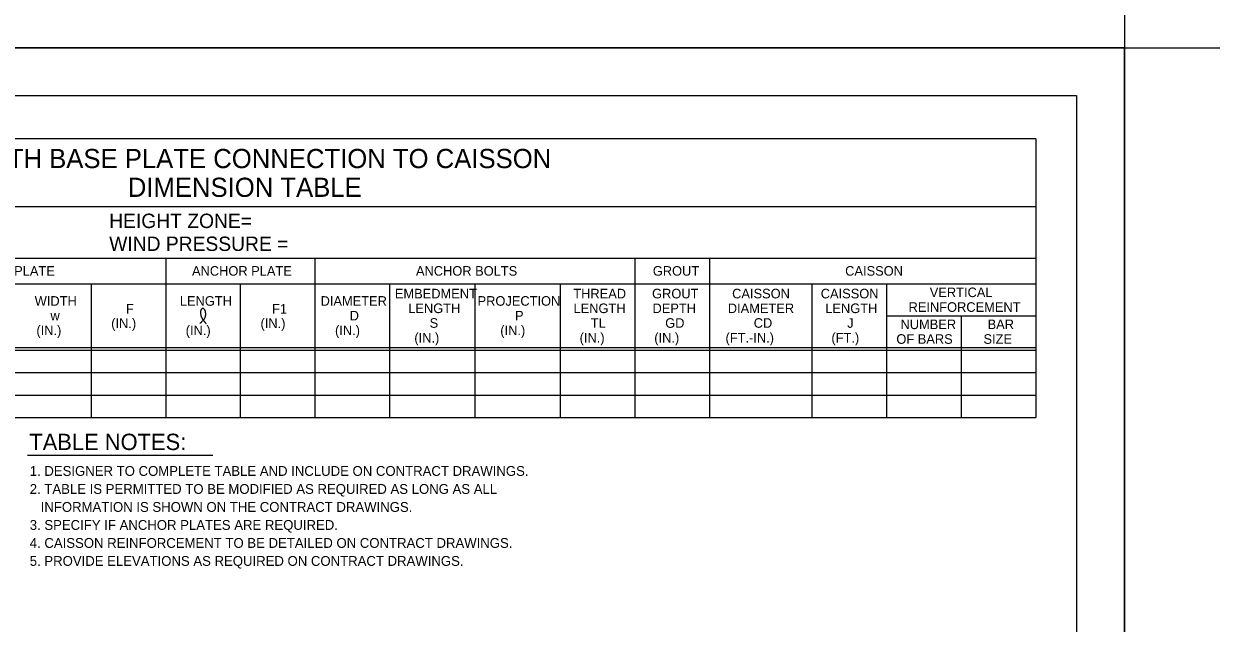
# Model space of a CAD drawing. Extents: x 3475 to 6558, y -3780 to 1166.
# Drawn here: x 4258.3 to 4629.5, y -202.4 to -14.8 of the extents above; entities that cross this region are included whole.
import ezdxf

# ---------------------------------------------------------------- set-up
doc = ezdxf.new("R2010")
doc.units = 0
for name, color, linetype in [('1', 7, 'Continuous'), ('2', 7, 'Continuous'), ('PLT-BNDY', 7, 'Continuous')]:
    doc.layers.add(name, color=color, linetype=linetype)

msp = doc.modelspace()

# ---------------------------------------------------------------- linework, layer by layer
at = {"layer": '1'}
for p, q in [((4574.64, -50.81), (4094.64, -50.81)), ((4574.64, -50.81), (4574.64, -138.01)), ((4574.64, -72.14), (4094.64, -72.14)), ((4094.64, -88.14), (4574.64, -88.14)), ((4302.64, -88.14), (4302.64, -138.01)), ((4349.3, -88.14), (4349.3, -138.01)), ((4449.3, -88.14), (4449.3, -138.01)), ((4472.64, -88.14), (4472.64, -138.01)), ((4094.64, -96.14), (4574.64, -96.14)), ((4279.31, -96.14), (4279.31, -138.01)), ((4325.97, -96.14), (4325.97, -138.01)), ((4372.64, -96.14), (4372.64, -138.01)), ((4399.3, -96.14), (4399.3, -138.01)), ((4425.97, -96.14), (4425.97, -138.01)), ((4504.64, -96.14), (4504.64, -138.01)), ((4527.97, -96.14), (4527.97, -138.01)), ((4527.97, -106.16), (4574.64, -106.16)), ((4551.31, -106.16), (4551.31, -138.01)), ((4094.64, -116.14), (4574.64, -116.14)), ((4094.64, -116.89), (4574.64, -116.89)), ((4094.64, -123.93), (4574.64, -123.93)), ((4094.64, -130.97), (4574.64, -130.97)), ((4094.64, -138.01), (4574.64, -138.01)), ((4259.47, -149.81), (4317.41, -149.81))]:
    msp.add_line(p, q, dxfattribs=at)
msp.add_spline([(4313.36, -108.55), (4313.56, -108.39), (4313.69, -108.25), (4313.89, -108.06), (4314.05, -107.89), (4314.33, -107.68), (4314.52, -107.43), (4314.7, -107.23), (4314.82, -107), (4314.93, -106.75), (4315.01, -106.52), (4315.09, -106.29), (4315.12, -106.09), (4315.15, -105.84), (4315.16, -105.62), (4315.15, -105.38), (4315.1, -105.13), (4315.06, -104.88), (4315, -104.65), (4314.91, -104.43), (4314.84, -104.29), (4314.74, -104.19), (4314.64, -104.1), (4314.55, -104.01), (4314.44, -103.95), (4314.35, -103.93), (4314.18, -103.93), (4314.09, -103.95), (4313.94, -104), (4313.84, -104.08), (4313.78, -104.17), (4313.72, -104.29), (4313.65, -104.4), (4313.61, -104.55), (4313.58, -104.65), (4313.54, -104.89), (4313.52, -105.06), (4313.54, -105.26), (4313.54, -105.45), (4313.58, -105.73), (4313.6, -105.96), (4313.64, -106.13), (4313.71, -106.35), (4313.81, -106.58), (4313.9, -106.77), (4314, -106.97), (4314.12, -107.2), (4314.32, -107.38), (4314.44, -107.59), (4314.57, -107.74), (4314.68, -107.92), (4314.82, -108.09), (4314.96, -108.27), (4315.06, -108.37), (4315.18, -108.51), (4315.28, -108.67)], degree=3, dxfattribs=at)
at = {"layer": '2'}
for p, q in [((3801.34, -37.31), (4587.34, -37.31)), ((4587.34, -37.31), (4587.34, -601.31))]:
    msp.add_line(p, q, dxfattribs=at)
at = {"layer": 'PLT-BNDY'}
for points in [[(3761.34, 571.69), (4602.34, 571.69), (4602.34, -22.31), (3761.34, -22.31)], [(3761.34, -22.31), (4602.34, -22.31), (4602.34, -616.31), (3761.34, -616.31)], [(4602.34, -22.31), (5443.34, -22.31), (5443.34, -616.31), (4602.34, -616.31)]]:
    msp.add_lwpolyline(points, close=True, dxfattribs=at)

# ---------------------------------------------------------------- texts
at = {"layer": '1'}
for s, height, p in [('STEEL POST WITH BASE PLATE CONNECTION TO CAISSON', 6.0001, (4191.77, -59.98)), ('DIMENSION TABLE', 6.0001, (4290.8, -68.98)), ('HEIGHT ZONE=', 4.5001, (4284.98, -78.73)), ('WIND PRESSURE =', 4.5001, (4284.98, -85.9)), ('BASE PLATE', 3, (4243.47, -93.64)), ('ANCHOR PLATE', 3, (4310.87, -93.64)), ('ANCHOR BOLTS', 3, (4380.87, -93.64)), ('GROUT', 3, (4454.91, -93.64)), ('CAISSON', 3, (4515.03, -93.64)), ('WIDTH', 3, (4261.7, -103.04)), ('LENGTH', 3, (4307.07, -103.04)), ('DIAMETER', 3, (4351.06, -103.04)), ('EMBEDMENT', 3, (4374.28, -100.74)), ('PROJECTION', 3, (4400.13, -103.04)), ('THREAD', 3, (4430.05, -100.74)), ('GROUT', 3, (4454.68, -100.74)), ('CAISSON', 3, (4479.7, -100.74)), ('CAISSON', 3, (4507.4, -100.74)), ('VERTICAL', 3, (4541.47, -100.35)), ('F', 3, (4290.23, -105.51)), ('F1', 3, (4335.9, -105.51)), ('LENGTH', 3, (4378.46, -105.34)), ('LENGTH', 3, (4430.12, -105.34)), ('DEPTH', 3, (4454.81, -105.34)), ('DIAMETER', 3, (4478.35, -105.34)), ('LENGTH', 3, (4508.82, -105.34)), ('REINFORCEMENT', 3, (4534.85, -104.95)), ('w', 3, (4266.62, -107.64)), ('(IN.)', 3, (4285.61, -110.01)), ('(IN.)', 3, (4332.28, -110.01)), ('D', 3, (4360.16, -107.64)), ('S', 3, (4385.14, -109.94)), ('P', 3, (4411.83, -107.64)), ('TL', 3, (4435.52, -109.94)), ('GD', 3, (4458.78, -109.94)), ('CD', 3, (4486.45, -109.94)), ('J', 3, (4515.67, -109.94)), ('NUMBER', 3, (4532.33, -110.35)), ('BAR', 3, (4559.56, -110.35)), ('(IN.)', 3, (4262.23, -112.24)), ('(IN.)', 3, (4308.9, -112.24)), ('(IN.)', 3, (4355.57, -112.24)), ('(IN.)', 3, (4407.23, -112.24)), ('(IN.)', 3, (4380.36, -114.54)), ('(IN.)', 3, (4432.03, -114.54)), ('(IN.)', 3, (4455.36, -114.54)), ('(FT.-IN.)', 3, (4477.63, -114.54)), ('(FT.)', 3, (4510.73, -114.54)), ('OF BARS', 3, (4531.04, -114.95)), ('SIZE', 3, (4558.27, -114.95)), ('TABLE NOTES:', 5.1169, (4260.02, -148.19)), ('1. DESIGNER TO COMPLETE TABLE AND INCLUDE ON CONTRACT DRAWINGS.', 3.072, (4260.15, -156.27)), ('2. TABLE IS PERMITTED TO BE MODIFIED AS REQUIRED AS LONG AS ALL', 3.072, (4260.15, -161.9)), ('   INFORMATION IS SHOWN ON THE CONTRACT DRAWINGS.', 3.072, (4260.15, -167.53)), ('3. SPECIFY IF ANCHOR PLATES ARE REQUIRED. ', 3.072, (4260.15, -173.16)), ('4. CAISSON REINFORCEMENT TO BE DETAILED ON CONTRACT DRAWINGS.', 3.072, (4260.15, -178.79)), ('5. PROVIDE ELEVATIONS AS REQUIRED ON CONTRACT DRAWINGS.', 3.072, (4260.15, -184.42))]:
    msp.add_text(s, height=height, dxfattribs=at).set_placement(p)

doc.saveas('drawing.dxf')
